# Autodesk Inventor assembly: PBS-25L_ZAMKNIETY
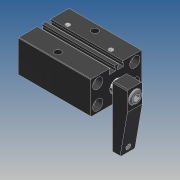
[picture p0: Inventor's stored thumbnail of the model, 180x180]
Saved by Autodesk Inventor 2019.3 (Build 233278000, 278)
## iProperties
Created: 2010-02
Part Number: PBS-25L_ZAMKNIETY
Material: Ogólny
Document SubType Name: Assembly
Designer: CADENGINEERING4
Sending System: PRO/ENGINEER BY PARAMETRIC TECHNOLOGY CORPORATION, 2007170
Preprocessor: PRO/ENGINEER BY PARAMETRIC TECHNOLOGY CORPORATION, 2007170
Title: PSB-25_ASM
Author: Administrator
Revision Number: 1LAST_VERSION
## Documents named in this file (6)
- E:\SERWER_ZAPAS\Pneumatic\PSB PNEUMATIC SWING\PSB-25\PBS-25L_ZAMKNIETY.iam
- E:\SERWER_ZAPAS\Pneumatic\PSB PNEUMATIC SWING\PSB-25\PSB-25BT.ipt
- E:\SERWER_ZAPAS\Pneumatic\PSB PNEUMATIC SWING\PSB-25\PSB-25HSG.ipt
- E:\SERWER_ZAPAS\Pneumatic\PSB PNEUMATIC SWING\PSB-25\PSB-25HG.ipt
- E:\SERWER_ZAPAS\Pneumatic\PSB PNEUMATIC SWING\PSB-25\PSB-25YB.ipt
- E:\SERWER_ZAPAS\Pneumatic\PSB PNEUMATIC SWING\PSB-25\M8X20.ipt
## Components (5 placed, 5 different names)
1. PSB-25BT_0 — Równoległe:1, Zestawiające:1, Zestawiające:2, Kątowe:1
2. PSB-25HSG_1 — Zestawiające:2, Zestawiające:4, Zestawiające:5, Zestawiające:8
3. PSB-25HG_2 — Równoległe:1, Zestawiające:1, Zestawiające:8
4. PSB-25YB_3 — Zestawiające:4, Zestawiające:5, Zestawiające:6, Zestawiające:7, Kątowe:1
5. M8X20_4 — Zestawiające:6, Zestawiające:7
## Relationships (9: Mate 7, Flush 1, Angle 1)
- Równoległe:1 [Flush]: PSB-25BT_0 ↔ PSB-25HG_2
- Zestawiające:1 [Mate]: PSB-25BT_0 ↔ PSB-25HG_2
- Zestawiające:2 [Mate]: PSB-25BT_0 ↔ PSB-25HSG_1
- Zestawiające:4 [Mate]: PSB-25HSG_1 ↔ PSB-25YB_3
- Zestawiające:5 [Mate]: PSB-25HSG_1 ↔ PSB-25YB_3
- Zestawiające:6 [Mate]: PSB-25YB_3 ↔ M8X20_4
- Zestawiające:7 [Mate]: PSB-25YB_3 ↔ M8X20_4
- Kątowe:1 [Angle]: PSB-25BT_0 ↔ PSB-25YB_3
- Zestawiające:8 [Mate]: PSB-25HSG_1 ↔ PSB-25HG_2
